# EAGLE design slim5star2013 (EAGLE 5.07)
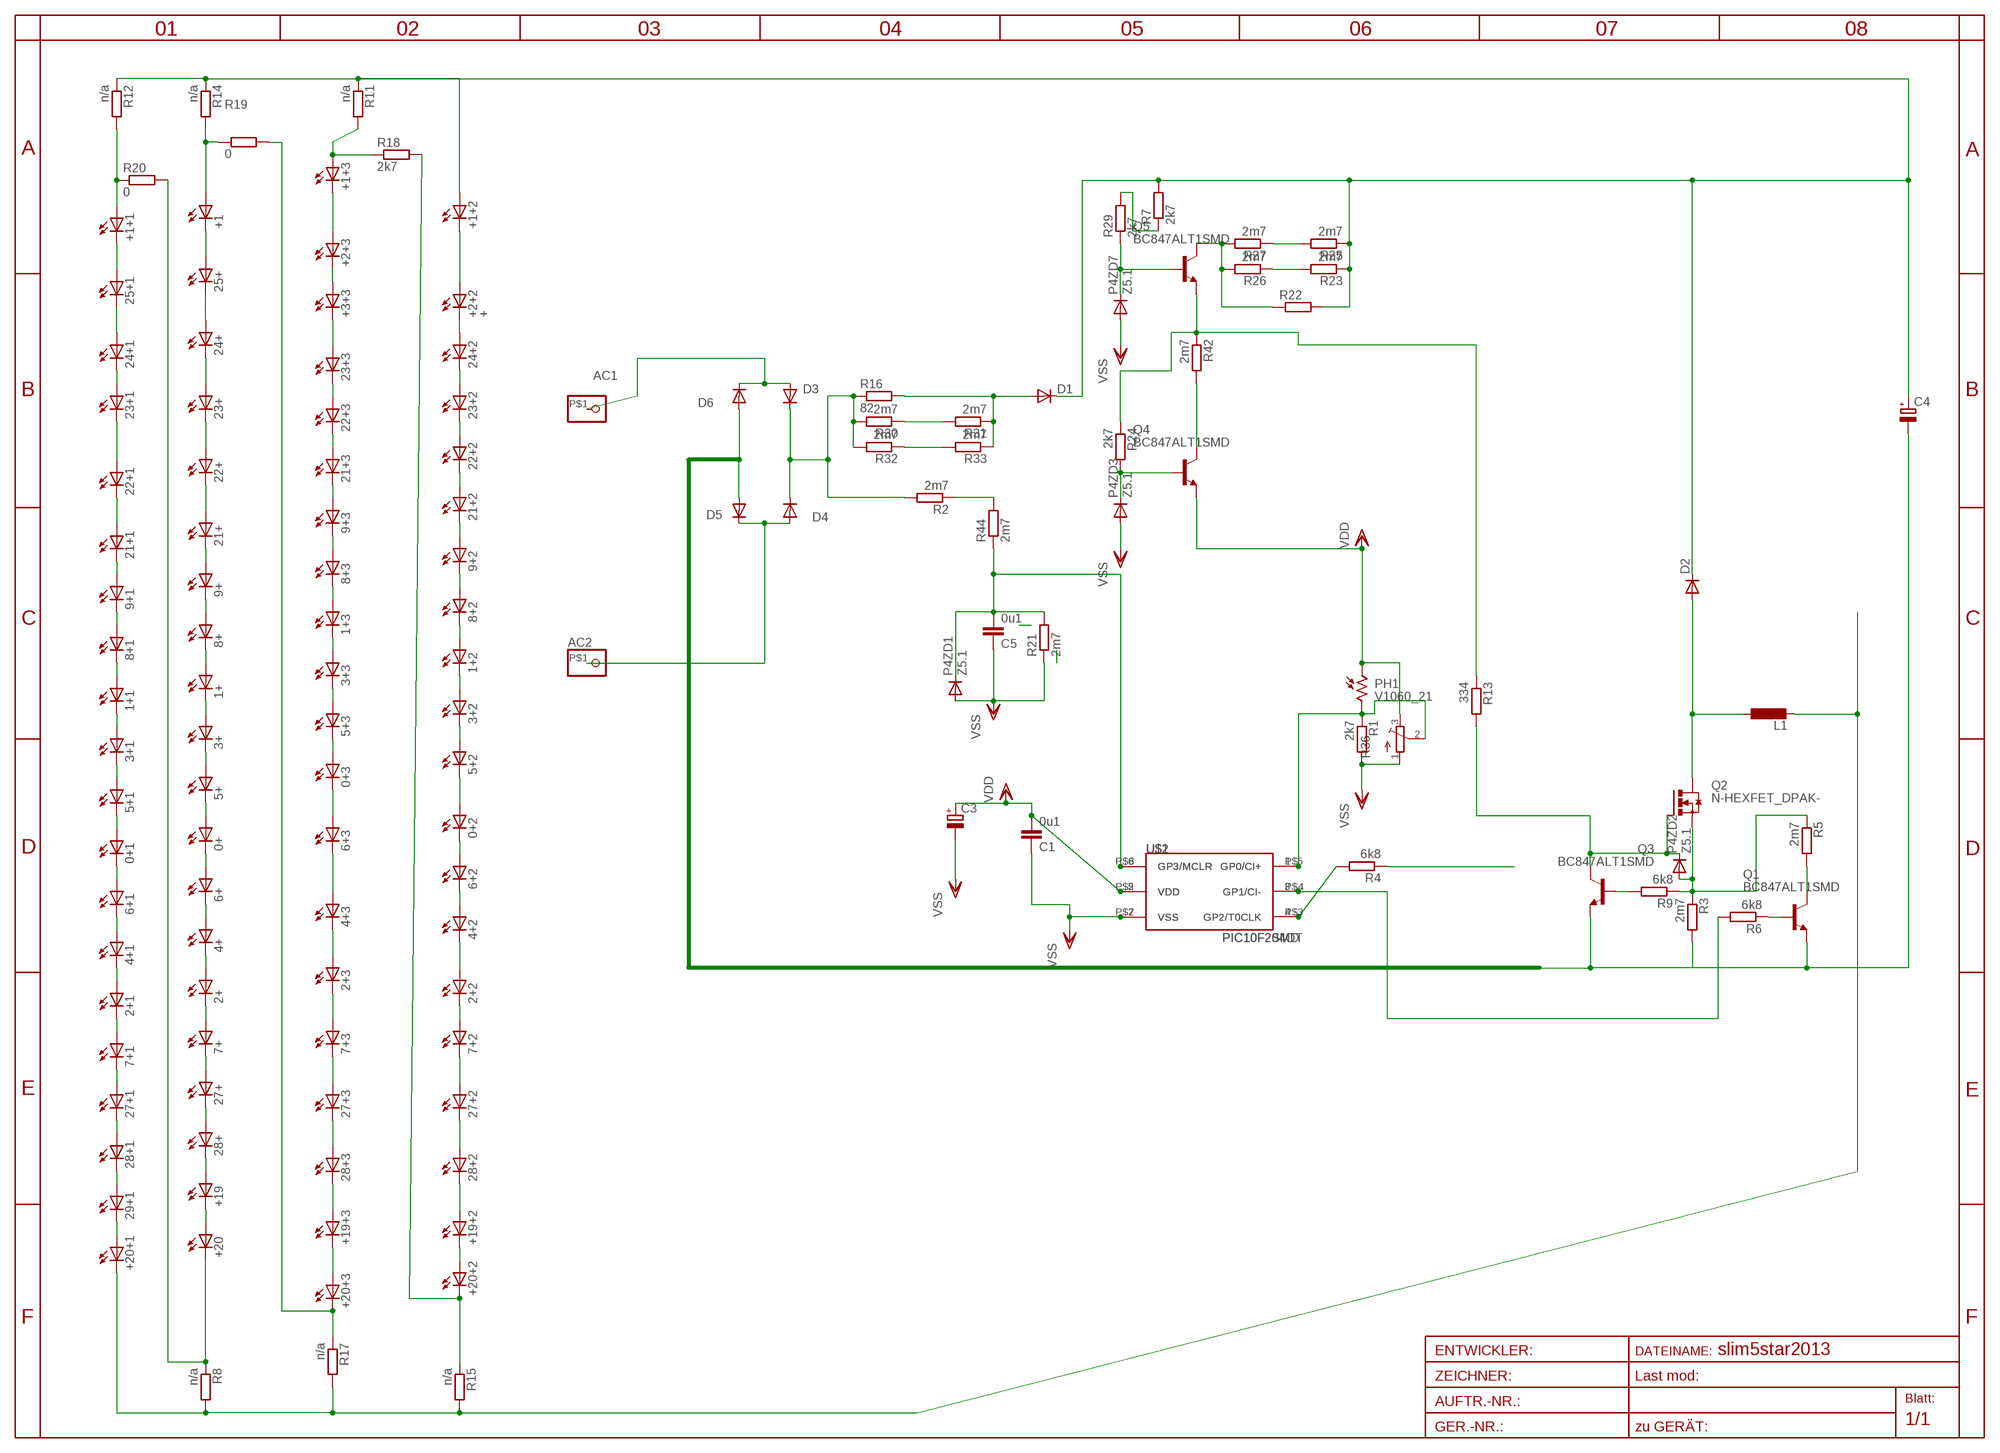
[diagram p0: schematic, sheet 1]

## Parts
0+  LED1210  [1210]
0+1  LED1210  [1210]
0+2  LED1210  [1210]
0+3  LED1210  [1210]
1+  LED1210  [1210]
1+1  LED1210  [1210]
1+2  LED1210  [1210]
1+3  LED1210  [1210]
2+  LED1210  [1210]
2+1  LED1210  [1210]
2+2  LED1210  [1210]
2+3  LED1210  [1210]
3+  LED1210  [1210]
3+1  LED1210  [1210]
3+2  LED1210  [1210]
3+3  LED1210  [1210]
4+  LED1210  [1210]
4+1  LED1210  [1210]
4+2  LED1210  [1210]
4+3  LED1210  [1210]
5+  LED1210  [1210]
5+1  LED1210  [1210]
5+2  LED1210  [1210]
5+3  LED1210  [1210]
6+  LED1210  [1210]
6+1  LED1210  [1210]
6+2  LED1210  [1210]
6+3  LED1210  [1210]
7+  LED1210  [1210]
7+1  LED1210  [1210]
7+2  LED1210  [1210]
7+3  LED1210  [1210]
8+  LED1210  [1210]
8+1  LED1210  [1210]
8+2  LED1210  [1210]
8+3  LED1210  [1210]
9+  LED1210  [1210]
9+1  LED1210  [1210]
9+2  LED1210  [1210]
9+3  LED1210  [1210]
21+  LED1210  [1210]
21+1  LED1210  [1210]
21+2  LED1210  [1210]
21+3  LED1210  [1210]
22+  LED1210  [1210]
22+1  LED1210  [1210]
22+2  LED1210  [1210]
22+3  LED1210  [1210]
23+  LED1210  [1210]
23+1  LED1210  [1210]
23+2  LED1210  [1210]
23+3  LED1210  [1210]
24+  LED1210  [1210]
24+1  LED1210  [1210]
24+2  LED1210  [1210]
25+  LED1210  [1210]
25+1  LED1210  [1210]
27+  LED1210  [1210]
27+1  LED1210  [1210]
27+2  LED1210  [1210]
27+3  LED1210  [1210]
28+  LED1210  [1210]
28+1  LED1210  [1210]
28+2  LED1210  [1210]
28+3  LED1210  [1210]
29+1  LED1210  [1210]
+1  LED1210  [1210]
+1+1  LED1210  [1210]
+1+2  LED1210  [1210]
+1+3  LED1210  [1210]
+2+2  +  LED1210  [1210]
+2+3  LED1210  [1210]
+3+3  LED1210  [1210]
+19  LED1210  [1210]
+19+2  LED1210  [1210]
+19+3  LED1210  [1210]
+20  LED1210  [1210]
+20+1  LED1210  [1210]
+20+2  LED1210  [1210]
+20+3  LED1210  [1210]
AC1  PINHD-1X1SMD  [SMD1X1]
AC2  PINHD-1X1SMD  [SMD1X1]
C1  0u1  C-EUC1206  [C1206]
C3  CPOL-EUE  [PANASONIC_E]
C4  CPOL-EUSANYO_SMD_F12  [SANYO-OSCON_SMD_F12]
C5  0u1  C-EUC1206  [C1206]
D1  DIODE-SMA-DO214  [SMA-DO214AC]
D2  DIODE-SMC  [SMC]
D3  DIODE-SOD80C  [SOD80C]
D4  DIODE-SOD80C  [SOD80C]
D5  DIODE-SOD80C  [SOD80C]
D6  DIODE-SOD80C  [SOD80C]
L1  L-EUPIS2816  [PIS2816]
P4ZD1  Z5.1  DIODE-MINIMELF  [MINIMELF]
P4ZD2  Z5.1  DIODE-MINIMELF  [MINIMELF]
P4ZD3  Z5.1  DIODE-MINIMELF  [MINIMELF]
P4ZD7  Z5.1  DIODE-MINIMELF  [MINIMELF]
PH1  V1060_21  [TO-5_V10]
Q1  BC847ALT1SMD  [SOT23]
Q2  N-HEXFET_DPAK-  [TO252]
Q3  BC847ALT1SMD  [SOT23]
Q4  BC847ALT1SMD  [SOT23]
Q5  BC847ALT1SMD  [SOT23]
R1  2k7  R-EU_R1206  [R1206]
R2  2m7  R-EU_R2010  [R2010]
R3  2m7  R-EU_R1206  [R1206]
R4  6k8  R-EU_R1206  [R1206]
R5  2m7  R-EU_R1210  [R1210]
R6  6k8  R-EU_R0805  [R0805]
R7  2k7  R-EU_R1206  [R1206]
R8  n/a  R-EU_R0402  [R0402]
R9  6k8  R-EU_R0805  [R0805]
R11  n/a  R-EU_R0402  [R0402]
R12  n/a  R-EU_R0402  [R0402]
R13  334  R-EU_R1206  [R1206]
R14  n/a  R-EU_R0402  [R0402]
R15  n/a  R-EU_R0402  [R0402]
R16  82  R-EU_SMD15  [SMDCARB15]
R17  n/a  R-EU_R0402  [R0402]
R18  2k7  R-EU_R0402  [R0402]
R19  0  R-EU_R0402  [R0402]
R20  0  R-EU_R0402  [R0402]
R21  2m7  R-EU_R1206  [R1206]
R22  R-EU_SMD15  [SMDCARB15]
R23  2m7  R-EU_R1210  [R1210]
R24  2k7  R-EU_R1206  [R1206]
R25  2m7  R-EU_R1210  [R1210]
R26  2m7  R-EU_R1210  [R1210]
R27  2m7  R-EU_R1210  [R1210]
R29  2k7  R-EU_R1206  [R1206]
R30  2m7  R-EU_R1210  [R1210]
R31  2m7  R-EU_R1210  [R1210]
R32  2m7  R-EU_R1210  [R1210]
R33  2m7  R-EU_R1210  [R1210]
R36  TRIM_EU-SM-42/43A  [SM-42/43A]
R42  2m7  R-EU_R1206  [R1206]
R44  2m7  R-EU_R2010  [R2010]
U$1  PIC10F2SMD  [DIL8SMD]
U$2  PIC10F204OT  [SOT23-6]

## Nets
AC1: Q5.2(E) R13.1 R24.1 R42.1
AC2: AC2.P$1 D4.A D5.C
BATT-: C4.- D5.A D6.A Q1.2(E) Q3.2(E) R3.2
D+: +1+2.P$1(A) C4.+ D1.K(C) D2.C R7.2 R11.1 R12.1 R14.1 R22.P$2 R23.1 R25.1
MINUS: +20+1.P$2(C) L1.2 R8.2 R15.2 R17.2
N$1: +1+3.P$1(A) R11.2 R18.1
N$2: +1+1.P$1(A) R12.2 R20.1
N$4: +20+3.P$2(C) R17.1 R19.2
N$5: Q4.3(C) R42.2
N$6: 8+.P$1(A) 9+.P$2(C)
N$7: +19.P$2(C) +20.P$1(A)
N$8: 28+.P$2(C) +19.P$1(A)
N$9: 27+.P$2(C) 28+.P$1(A)
N$10: 29+1.P$2(C) +20+1.P$1(A)
N$11: 28+1.P$2(C) 29+1.P$1(A)
N$12: 2+.P$2(C) 7+.P$1(A)
N$13: 7+.P$2(C) 27+.P$1(A)
N$14: 2+.P$1(A) 4+.P$2(C)
N$15: 4+.P$1(A) 6+.P$2(C)
N$16: 0+.P$2(C) 6+.P$1(A)
N$17: 0+.P$1(A) 5+.P$2(C)
N$18: 3+.P$2(C) 5+.P$1(A)
N$19: 1+.P$2(C) 3+.P$1(A)
N$20: 1+.P$1(A) 8+.P$2(C)
N$21: 27+1.P$2(C) 28+1.P$1(A)
N$22: 2+1.P$1(A) 4+1.P$2(C)
N$23: 9+.P$1(A) 21+.P$2(C)
N$24: 21+.P$1(A) 22+.P$2(C)
N$25: 22+.P$1(A) 23+.P$2(C)
N$26: 24+.P$1(A) 25+.P$2(C)
N$27: 25+.P$1(A) +1.P$2(C)
N$28: 23+.P$1(A) 24+.P$2(C)
N$29: 4+1.P$1(A) 6+1.P$2(C)
N$30: 0+1.P$2(C) 6+1.P$1(A)
N$31: 0+1.P$1(A) 5+1.P$2(C)
N$32: 3+1.P$2(C) 5+1.P$1(A)
N$33: 1+1.P$2(C) 3+1.P$1(A)
N$34: 1+1.P$1(A) 8+1.P$2(C)
N$35: 9+1.P$1(A) 21+1.P$2(C)
N$36: 21+1.P$1(A) 22+1.P$2(C)
N$37: 22+1.P$1(A) 23+1.P$2(C)
N$38: 25+1.P$1(A) +1+1.P$2(C)
N$39: 24+1.P$1(A) 25+1.P$2(C)
N$40: 23+1.P$1(A) 24+1.P$2(C)
N$41: 2+1.P$2(C) 7+1.P$1(A)
N$42: 7+1.P$2(C) 27+1.P$1(A)
N$43: 8+1.P$1(A) 9+1.P$2(C)
N$45: +1.P$1(A) R14.2 R19.1
N$46: +19+2.P$2(C) +20+2.P$1(A)
N$47: 28+2.P$2(C) +19+2.P$1(A)
N$48: 27+2.P$2(C) 28+2.P$1(A)
N$49: 2+2.P$1(A) 4+2.P$2(C)
N$50: 4+2.P$1(A) 6+2.P$2(C)
N$51: 0+2.P$2(C) 6+2.P$1(A)
N$52: 0+2.P$1(A) 5+2.P$2(C)
N$53: 3+2.P$2(C) 5+2.P$1(A)
N$54: 1+2.P$2(C) 3+2.P$1(A)
N$55: 1+2.P$1(A) 8+2.P$2(C)
N$56: 9+2.P$1(A) 21+2.P$2(C)
N$57: 21+2.P$1(A) 22+2.P$2(C)
N$58: 22+2.P$1(A) 23+2.P$2(C)
N$59: +1+2.P$2(C) +2+2.P$1(A)
N$60: 24+2.P$1(A) +2+2.P$2(C)
N$61: 23+2.P$1(A) 24+2.P$2(C)
N$62: 2+2.P$2(C) 7+2.P$1(A)
N$63: 7+2.P$2(C) 27+2.P$1(A)
N$64: 8+2.P$1(A) 9+2.P$2(C)
N$65: +20+2.P$2(C) R15.1 R18.2
N$66: +20.P$2(C) R8.1 R20.2
N$67: +19+3.P$2(C) +20+3.P$1(A)
N$68: 28+3.P$2(C) +19+3.P$1(A)
N$69: 27+3.P$2(C) 28+3.P$1(A)
N$70: 2+3.P$1(A) 4+3.P$2(C)
N$71: 4+3.P$1(A) 6+3.P$2(C)
N$72: 0+3.P$2(C) 6+3.P$1(A)
N$73: 0+3.P$1(A) 5+3.P$2(C)
N$74: 3+3.P$2(C) 5+3.P$1(A)
N$75: 1+3.P$2(C) 3+3.P$1(A)
N$76: 1+3.P$1(A) 8+3.P$2(C)
N$77: 9+3.P$1(A) 21+3.P$2(C)
N$78: 21+3.P$1(A) 22+3.P$2(C)
N$79: 22+3.P$1(A) 23+3.P$2(C)
N$80: +1+3.P$2(C) +2+3.P$1(A)
N$81: +2+3.P$2(C) +3+3.P$1(A)
N$82: 23+3.P$1(A) +3+3.P$2(C)
N$83: 2+3.P$2(C) 7+3.P$1(A)
N$84: 7+3.P$2(C) 27+3.P$1(A)
N$85: 8+3.P$1(A) 9+3.P$2(C)
N$86: D1.A R16.P$2 R31.1 R33.1
N$87: D2.A L1.1 Q2.3(D)
N$88: PH1.2 R1.1 R36.2(S) U$1.P$5(GP0/CI+) U$2.1(GP0/CI+)
N$91: D3.C D4.C R2.2 R16.P$1 R30.2 R32.2
N$92: Q5.3(C) R22.P$1 R26.2 R27.2
N$93: AC1.P$1 D3.A D6.C
N$94: P4ZD2.C Q2.1(G) Q3.3(C) R13.2
N$95: R4.2 U$1.P$3(GP2/T0CLK) U$2.4(GP2/T0CLK)
N$96: C5.2 P4ZD1.C R21.2 R44.1 U$1.P$8(GP3/MCLR) U$2.6(GP3/MCLR)
N$97: R2.1 R44.2
N$98: Q1.1(B) R6.1
N$99: R23.2 R26.1
N$100: R25.2 R27.1
N$101: Q1.3(C) R5.2
N$102: R6.2 U$1.P$4(GP1/CI-) U$2.3(GP1/CI-)
N$103: P4ZD3.C Q4.1(B) R24.2
N$104: P4ZD7.C Q5.1(B) R29.1
N$105: P4ZD2.A Q2.2(S) R3.1 R5.1 R9.1
N$106: R7.1 R29.2
N$107: R30.1 R31.2
N$108: R32.1 R33.2
N$109: Q3.1(B) R9.2
PIR: R4.1
VDD: C1.2 C3.+ PH1.1 Q4.2(E) R36.3(E) U$1.P$2(VDD) U$2.5(VDD)
VSS: C1.1 C3.- C5.1 P4ZD1.A P4ZD3.A P4ZD7.A R1.2 R21.1 R36.1(A) U$1.P$7(VSS) U$2.2(VSS)

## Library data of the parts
0+ 0+1-0+3 1+ 1+1-1+3 2+ 2+1-2+3 3+ 3+1-3+3 4+ 4+1-4+3 5+ 5+1-5+3 6+ 6+1-6+3 7+ 7+1-7+3 8+ 8+1-8+3 9+ 9+1-9+3 21+ 21+1-21+3 22+ 22+1-22+3 23+ 23+1-23+3 24+ 24+1 24+2 25+ 25+1 27+ 27+1-27+3 28+ 28+1-28+3 29+1 +1 +1+1-+1+3 +2+2 +2+3 +3+3 +19 +19+2 +19+3 +20 +20+1-+20+3 = led(2):LED: LED
AC1 AC2 = pinhead:PINHD-1X1: PIN HEADER
C1 C5 = rcl:C-EU: CAPACITOR, European symbol
C3 C4 = rcl-2:CPOL-EU: POLARIZED CAPACITOR, European symbol
D1-D6 P4ZD1-P4ZD3 P4ZD7 = diode:DIODE-: DIODE
L1 = rcl:L-EU: INDUCTOR, European symbol
PH1 = photo-elements:?1060*: Sensor Street Light control
Q1 Q3-Q5 = transistor-npn:BC847*: NPN Transistor
Q2 = transistor-power:N-HEXFET_?-*: HEXFET® Power MOSFET
R1 R2 R4 R7 R8 R11-R15 R17-R21 R23-R27 R29-R33 R42 R44 = rcl-2:R-EU_: RESISTOR, European symbol
R3 R5 R6 R9 R16 R22 = rcl:R-EU_: RESISTOR, European symbol
R36 = pot:TRIM_EU-: POTENTIOMETER
U$1 U$2 = microchip-5:PIC10F2*: uPC nW 0,25/0,5k Program Flash memory Comparator

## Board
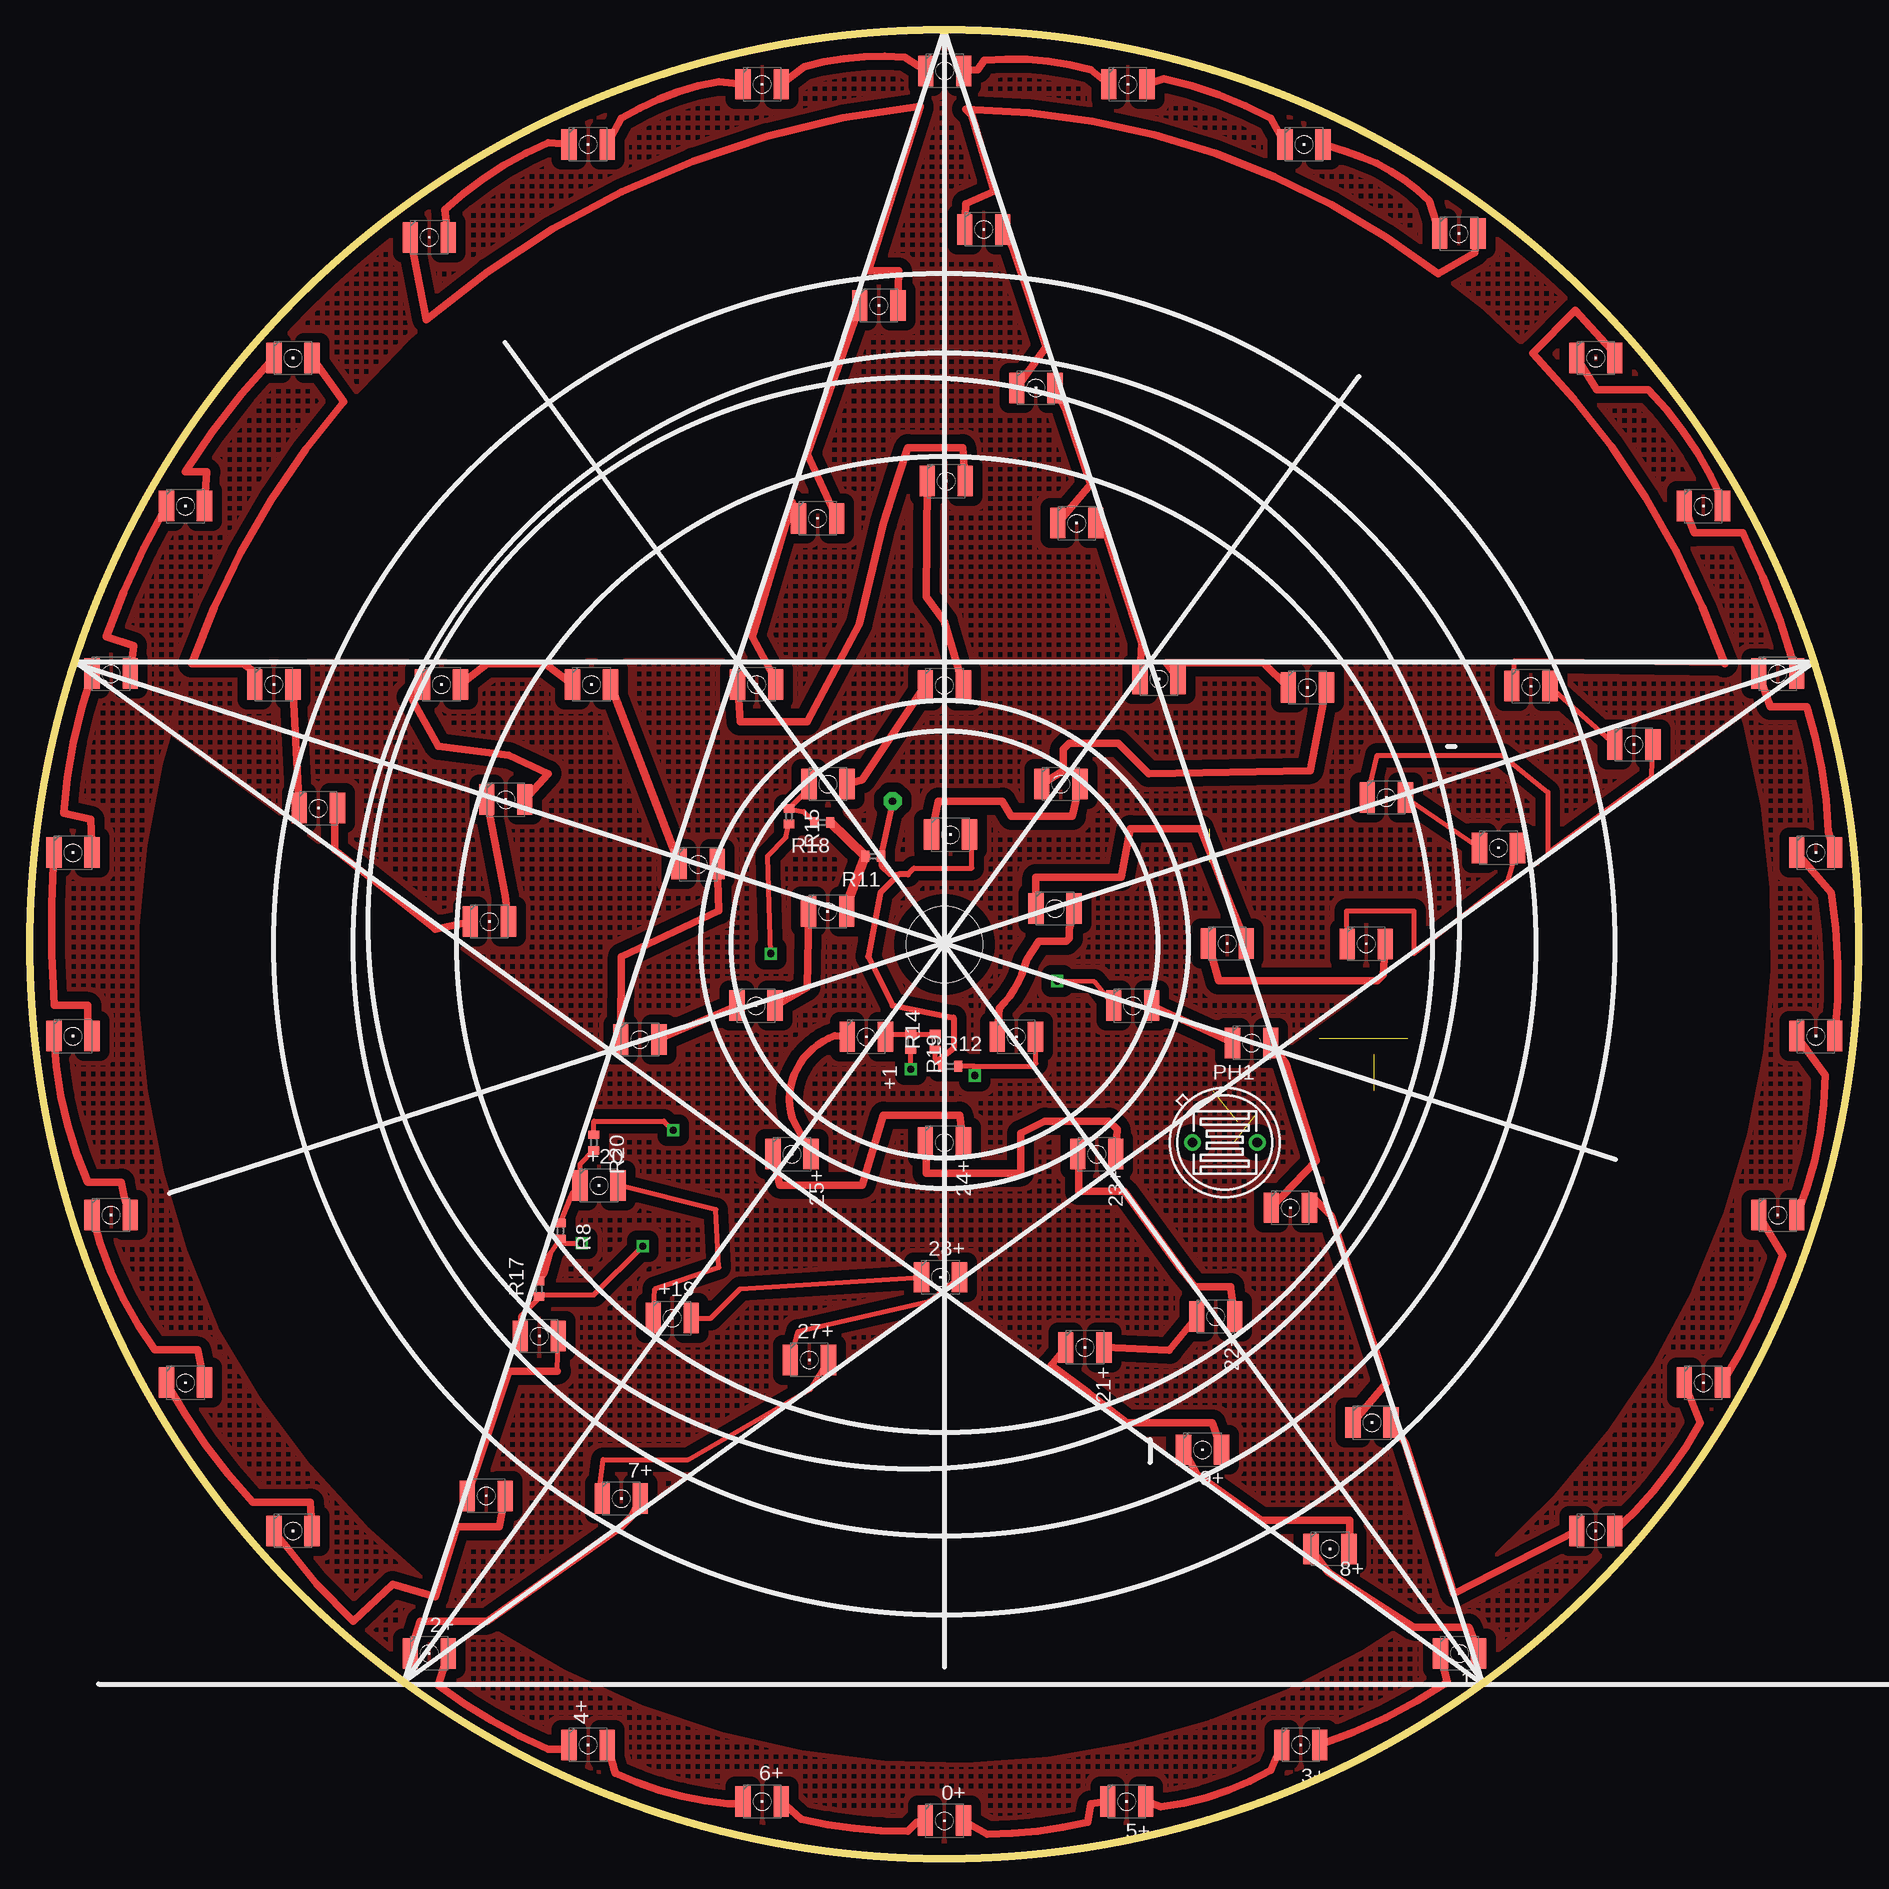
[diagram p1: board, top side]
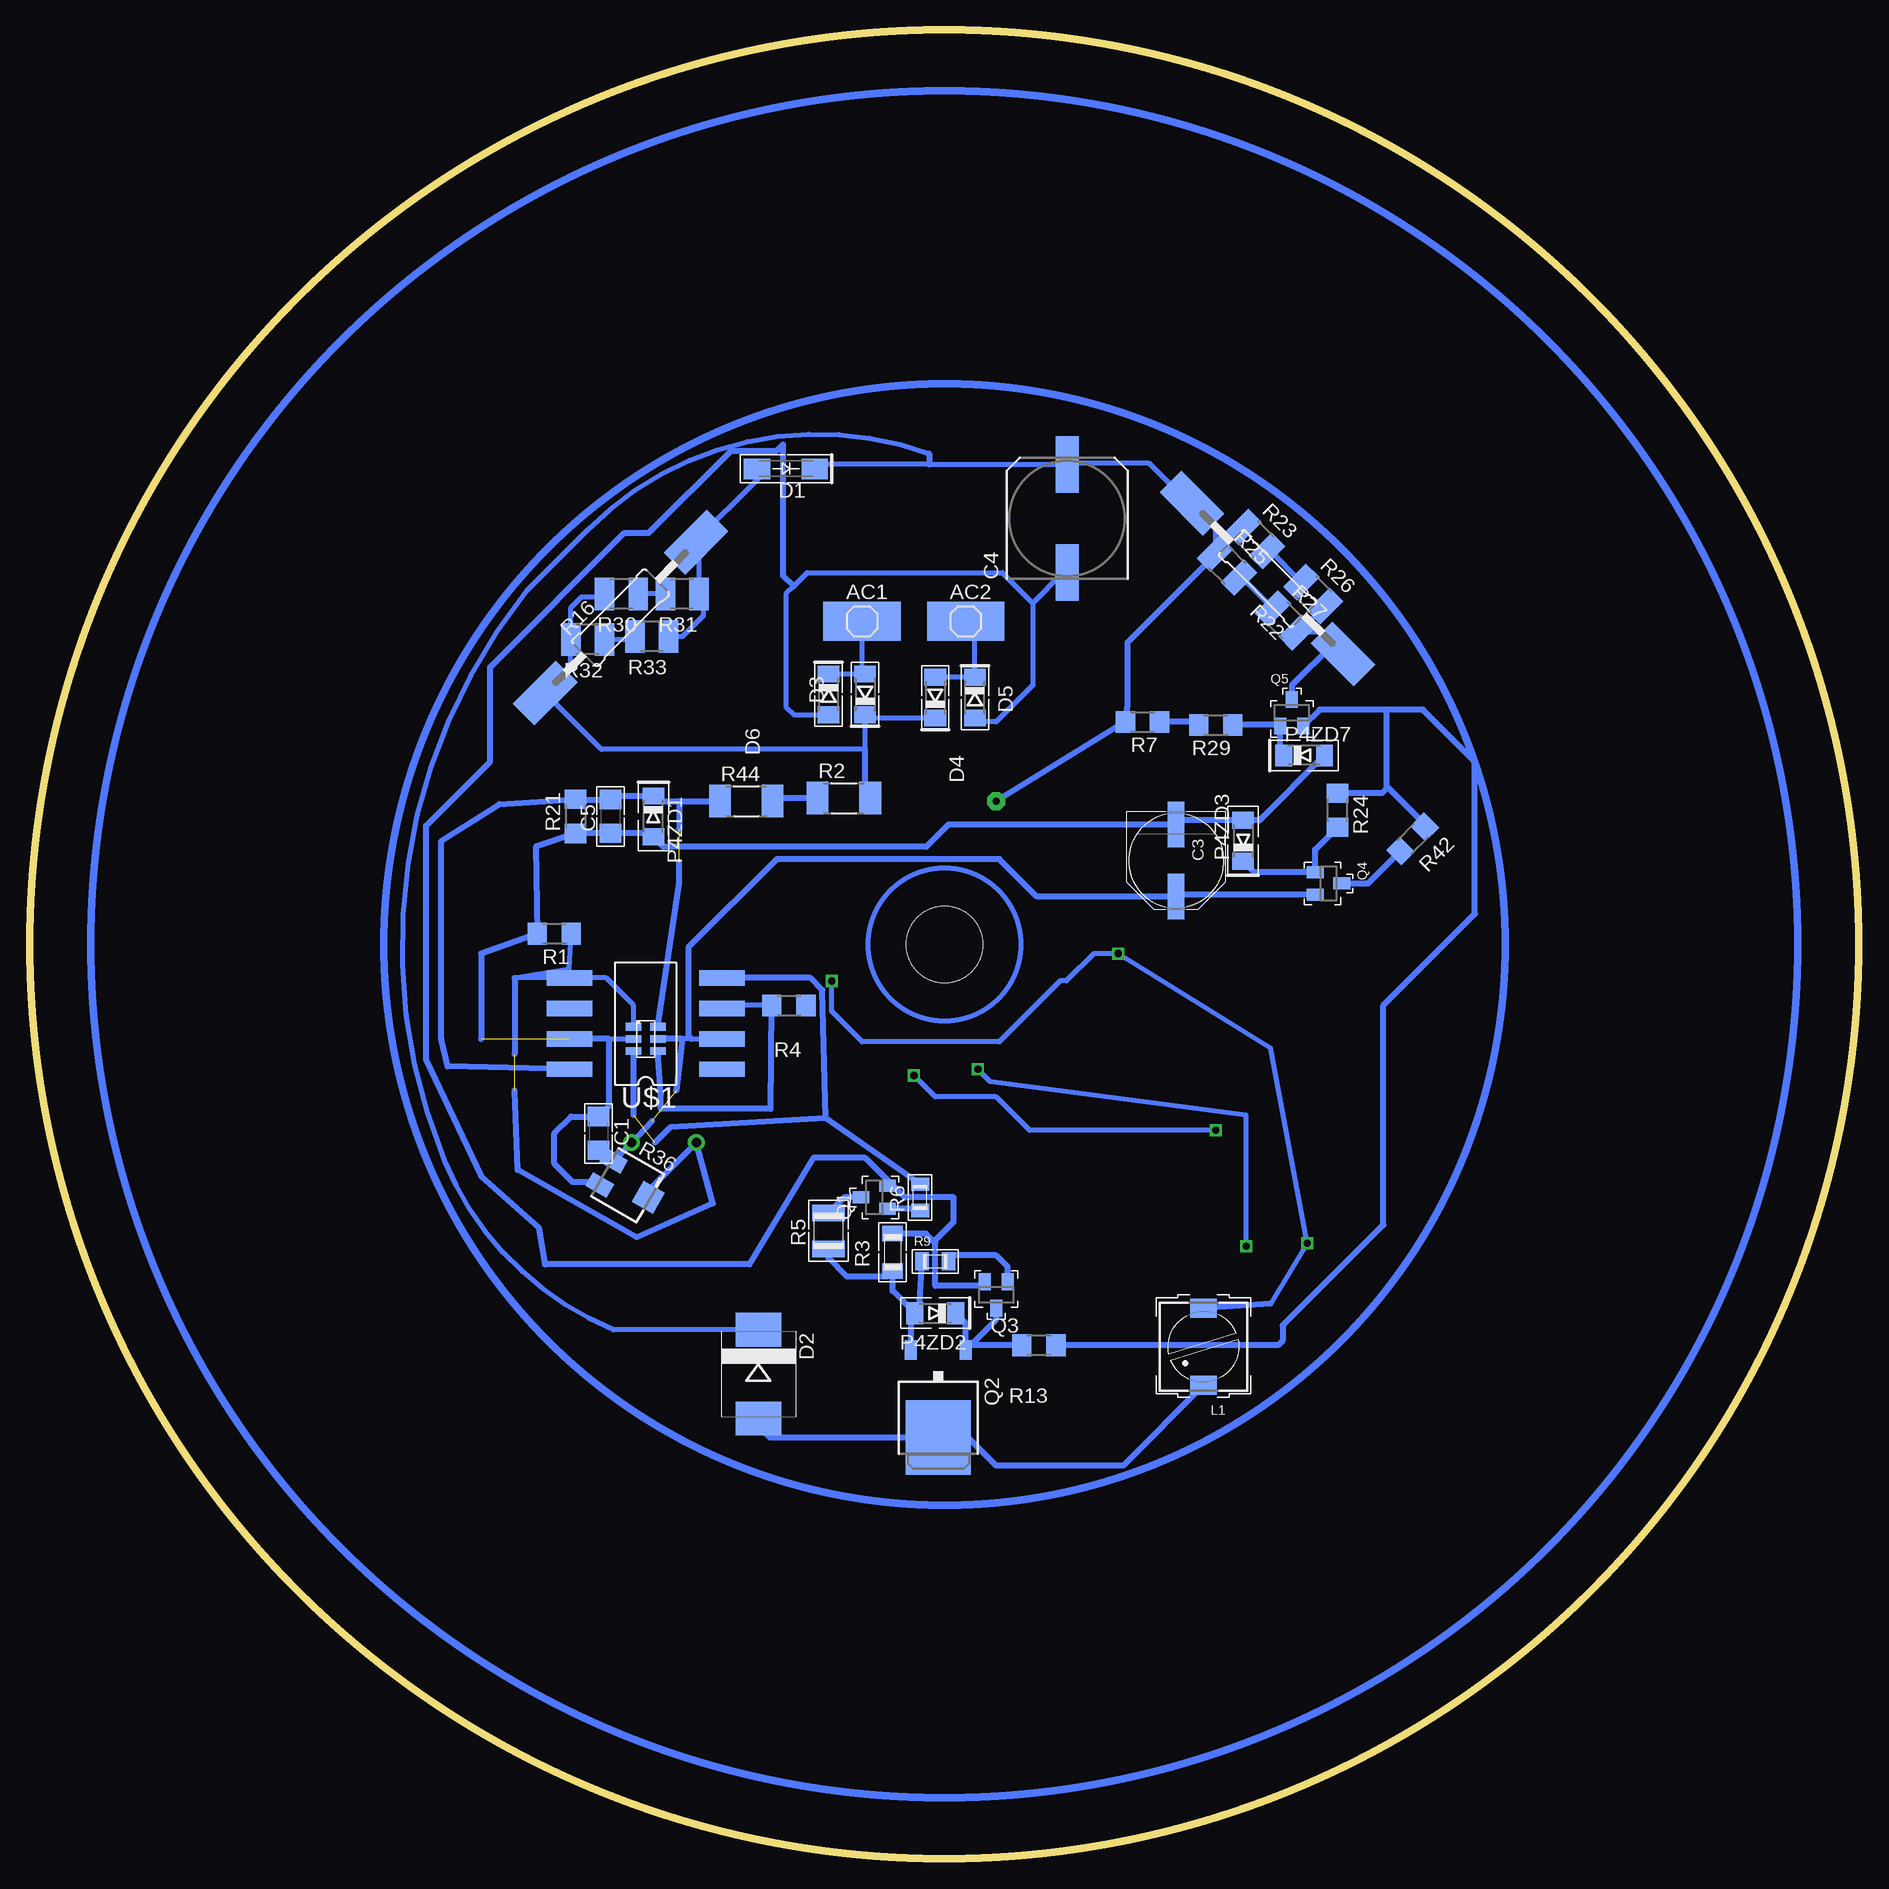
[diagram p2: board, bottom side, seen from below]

Size 152.4 x 152.4 mm. Coordinates in mm from the lower left corner, seen from the top.
Outline: circle at 76.2,76.2 radius 76.2
Copper layers (1*16): Top 0.035mm / dielectric 1.5mm / Bottom 0.035mm
Design rules "default": minimum track width 10mil, minimum drill 24mil, track to track 8mil, track to pad 8mil, pad to pad 8mil, via to via 8mil, smd to smd 8mil, copper to edge 40mil, drill to drill 8mil, minimum pad ring 10mil, minimum via ring 8mil, stop-mask expansion 4mil, vias tented up to drill 0mil, thermal gap 10mil
Holes 6.35 mm at 76.2,76.2

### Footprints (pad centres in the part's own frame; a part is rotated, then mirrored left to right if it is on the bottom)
1210 = smd 1.27 x 2.54: P$1 1.587,0; P$2 -1.587,0
SMD1X1 = smd 6.452 x 3.251: P$1 0,0
C1206 = smd 1.6 x 1.8: 1 -1.4,0; 2 1.4,0
PANASONIC_E = smd 3.8 x 1.4: + 3,0; - -3,0
SANYO-OSCON_SMD_F12 = smd 4.7 x 1.9: + 4.5,0; - -4.5,0
SMA-DO214AC = smd 2.2 x 1.7: A 2.4,0; K -2.4,0
SMC = smd 2.8 x 3.8: A 3.7,0; C -3.7,0
SOD80C = smd 1.4 x 1.8: A 1.7,0; C -1.7,0
PIS2816 = smd 2.2 x 1.6: 1 0,3.2; 2 0,-3.2
MINIMELF = smd 1.4 x 1.8: A 1.7,0; C -1.7,0
TO-5_V10 = drill 0.8 pad 1.4 round: 1 -2.7,0; 2 2.7,0
SOT23 = smd 1 x 1.4: 1 -0.95,-1.1; 2 0.95,-1.1; 3 0,1.1
TO252 = smd 1 x 1.6: 1 -2.28,-3.53; 2 2.28,-3.53 | smd 5.4 x 6.2: 3 0,3.77
R1206 = smd 1.6 x 1.803: 1 -1.422,0; 2 1.422,0
R2010 = smd 1.8 x 2.7: 1 -2.2,0; 2 2.2,0
R1206' = smd 1.3 x 1.7: 1 -1.55,0; 2 1.55,0
R1210 = smd 1.4 x 2.7: 1 -1.5,0; 2 1.5,0
R0805 = smd 1.1 x 1.5: 1 -1.1,0; 2 1.1,0
R0402 = smd 0.7 x 0.9: 1 -0.65,0; 2 0.65,0
SMDCARB15 = smd 5.08 x 2.54: P$1 -8.89,0; P$2 8.89,0
R1210' = smd 1.6 x 2.7: 1 -1.4,0; 2 1.4,0
SM-42/43A = smd 2 x 1.3: 1 2,1.15; 3 2,-1.15 | smd 2 x 2: 2 -2,0
DIL8SMD = smd 1.27 x 3.81: P$1 -3.81,-6.35; P$2 -1.27,-6.35; P$3 1.27,-6.35; P$4 3.81,-6.35; P$5 3.81,6.35; P$6 1.27,6.35; P$7 -1.27,6.35; P$8 -3.81,6.35
SOT23-6 = smd 0.635 x 1.27: 1 -1.016,-1.016; 2 0,-1.016; 3 1.016,-1.016; 4 1.016,1.016; 5 0,1.016; 6 -1.016,1.016

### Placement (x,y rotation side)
0+  76.2,3.17 0 top
0+1  148.82,83.85 0 top
0+2  61.01,147.88 0 top
0+3  12.95,112.73 0 top
1+  119.13,17.12 0 top
1+1  130.48,125.07 0 top
1+2  106.17,142.88 0 top
1+3  24.03,87.55 0 top
2+  33.27,17.12 0 top
2+1  139.45,39.67 0 top
2+2  70.74,129.44 0 top
2+3  3.58,68.55 0 top
3+  105.89,9.5 0 top
3+1  139.45,112.73 0 top
3+2  91.49,147.88 0 top
3+3  20.32,97.87 0 top
4+  46.51,9.5 0 top
4+1  145.64,53.64 0 top
4+2  33.27,135.13 0 top
4+3  3.58,83.85 0 top
5+  91.39,4.78 0 top
5+1  145.64,98.76 0 top
5+2  76.23,149 0 top
5+3  21.92,125.07 0 top
6+  61.01,4.78 0 top
6+1  148.82,68.55 0 top
6+2  46.51,142.88 0 top
6+3  6.76,98.76 0 top
7+  49.28,30.02 0 top
7+1  130.48,27.33 0 top
7+2  65.63,111.71 0 top
7+3  6.76,53.64 0 top
8+  108.33,25.83 0 top
8+1  125.07,97.71 0 top
8+2  119.08,135.43 0 top
8+3  38.28,78.11 0 top
9+  97.71,34.09 0 top
9+1  133.65,92.86 0 top
9+2  79.48,135.79 0 top
9+3  39.65,88.27 0 top
21+  87.91,42.62 0 top
21+1  113.03,88.44 0 top
21+2  83.82,122.58 0 top
21+3  34.29,97.87 0 top
22+  98.81,45.19 0 top
22+1  122.38,84.25 0 top
22+2  87.22,111.3 0 top
22+3  46.79,97.87 0 top
23+  88.9,58.72 0 top
23+1  111.35,76.25 0 top
23+2  94.08,98.32 0 top
23+3  55.68,82.88 0 top
24+  76.2,59.69 0 top
24+1  99.77,76.28 0 top
24+2  106.45,97.61 0 top
25+  63.5,58.72 0 top
25+1  85.42,79.2 0 top
27+  64.95,41.58 0 top
27+1  111.84,36.35 0 top
27+2  60.55,97.87 0 top
27+3  12.95,39.67 0 top
28+  75.87,48.46 0 top
28+1  105.03,54.25 0 top
28+2  76.35,114.81 0 top
28+3  21.92,27.33 0 top
29+1  101.8,68 0 top
+1  69.7,68.5 0 top
+1+1  82.19,68.5 0 top
+1+2  76.71,85.34 0 top
+1+3  66.47,78.94 0 top
+2+2  85.9,89.56 0 top
+2+3  60.5,71.09 0 top
+3+3  50.83,68.28 0 top
+19  53.52,45.06 0 top
+19+2  76.2,97.79 0 top
+19+3  38.02,30.25 0 top
+20  47.42,56.11 0 top
+20+1  91.9,71.09 0 top
+20+2  66.5,89.56 0 top
+20+3  42.44,43.56 0 top
AC1  83.06,103.12 0 bottom
AC2  74.42,103.12 0 bottom
C1  105.03,60.45 270 bottom
C3  56.9,83.19 270 bottom
C4  65.97,111.7 90 bottom
C5  104.01,86.87 90 bottom
D1  89.41,115.82 180 bottom
D2  91.69,40.39 270 bottom
D3  82.8,97.03 90 bottom
D4  76.96,96.77 90 bottom
D5  73.66,96.77 270 bottom
D6  85.85,97.03 270 bottom
L1  54.61,42.67 180 bottom
P4ZD1  100.46,86.87 270 bottom
P4ZD2  76.96,45.47 180 bottom
P4ZD3  51.31,84.84 90 bottom
P4ZD7  46.23,91.95 0 bottom
PH1  99.57,59.69 180 top
Q1  82.04,55.12 90 bottom
Q2  76.71,38.86 180 bottom
Q3  71.88,46.99 180 bottom
Q4  44.2,81.28 270 bottom
Q5  47.24,95.5 0 bottom
R1  108.71,77.09 180 bottom
R2  84.58,88.39 0 bottom
R3  2m7  [R1206']  80.52,50.55 90 bottom
R4  89.15,71.12 180 bottom
R5  85.85,52.32 90 bottom
R6  78.23,55.12 90 bottom
R7  59.69,94.74 180 bottom
R8  44.2,52.32 270 top
R9  76.96,49.78 0 bottom
R11  70.26,83.55 180 top
R12  76.71,66.04 0 top
R13  68.33,42.8 180 bottom
R14  75.44,68.07 90 top
R15  63.25,86.87 270 top
R16  103.18,103.43 45 bottom
R17  42.42,47.5 90 top
R18  66.04,86.36 180 top
R19  73.41,68.07 270 top
R20  46.99,59.69 270 top
R21  106.93,86.87 90 bottom
R22  49.28,106.68 135 bottom
R23  2m7  [R1210']  50.29,109.98 315 bottom
R24  43.43,87.38 270 bottom
R25  2m7  [R1210']  52.65,107.77 315 bottom
R26  2m7  [R1210']  45.47,105.41 315 bottom
R27  2m7  [R1210']  47.83,103.2 315 bottom
R29  53.59,94.49 180 bottom
R30  2m7  [R1210']  103.12,105.41 180 bottom
R31  2m7  [R1210']  98.04,105.41 180 bottom
R32  2m7  [R1210']  105.92,101.6 180 bottom
R33  2m7  [R1210']  100.58,101.85 180 bottom
R36  102.62,56.13 150 bottom
R42  37.19,84.98 225 bottom
R44  92.71,88.14 0 bottom
U$1  101.09,69.6 90 bottom
U$2  101.09,68.33 270 bottom

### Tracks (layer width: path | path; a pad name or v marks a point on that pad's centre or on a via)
AC1
  Bottom 0.5: R13.1 48.39,42.8 48.01,43.18 48.01,44.45 39.62,52.83 39.62,71.12 32,78.74 32,91.44 36.32,95.76 39.37,95.76 | 39.37,95.76 44.94,95.76 Q5.2 | R42.1 36.18,86.22 39.24,89.28 | 39.24,89.28 39.37,89.41 39.37,95.76 | R24.1 39.73,88.8 39.24,89.28
AC2
  Bottom 0.406: AC2.P$1 73.66,103.12 D5.C D4.A
BATT-
  Bottom 0.406: D6.A 88.72,95.33 89.41,96.01 89.41,105.41 88.77,106.05 87.63,107.19 71.37,107.19 68.83,104.65 | 68.83,104.65 68.83,97.79 71.88,94.74 73.33,94.74 D5.A | C4.- 66.28,107.2 68.83,104.65
  Bottom 0.5: R3.2 77.75,52.1 77.09,51.44 | 77.09,51.44 76.96,51.31 76.96,47.75 73.17,47.75 Q3.2 | 80.45,56.07 Q1.2 | 80.45,56.07 79.5,55.12 75.44,55.12 75.44,53.09 77.09,51.44 | 80.45,56.07 82.8,58.42 87.12,58.42 92.46,49.53 109.47,49.53 109.98,52.58 114.81,56.9 119.38,66.55 119.38,86.11 114.05,91.44 114.05,99.31 102.87,110.49 100.84,110.49 93.98,117.35 90.17,117.35 89.66,117.86 89.66,106.93 88.77,106.05
D+  (via drill 0.6 pad 1.5)
  Top 0.406: R14.1 75.44,66.66 75.62,66.48 R12.1 | R11.1 70.91,82.76 71.63,82.04 73.15,82.04 73.66,82.55 78.49,82.55 78.49,85.15 +1+2.P$1
  Top 0.5: 73.15,82.04 72.39,82.04 70.87,80.52 69.85,75.18 71.88,71.12 76.96,70.1 76.96,67.56 75.62,66.48 | v71.88,88.14 R11.1
  Bottom 0.406: R23.1 53.49,108.76 R25.1 53.64,111.05 R22.P$2 55.82,112.97 59.18,116.33 65.84,116.33 C4.+ 77.47,116.2 87.33,116.2 D1.K | D2.C 103.78,44.09 arc45 117.86,58.17 arc61 111,105.66 105.92,110.74 arc65 77.47,117.09
  Bottom 0.5: R25.1 53.64,108.66 60.96,101.35 60.96,96.16 R7.2 v71.88,88.14 | 77.47,117.09 77.47,116.2
MINUS  (via drill 0.6)
  Top 0.406: R15.2 62.99,85.09 61.47,83.57 v61.72,75.44 | 43.32,50.43 R17.2 42.93,48.77 43.43,50.55 R8.2 44.56,51.31 v45.97,51.31 | +20+1.P$2 88.67,73.13 v85.6,73.15
  Bottom 0.406: v85.6,73.15 85.6,70.61 83.06,68.07 71.63,68.07 66.55,73.15 66.04,73.15 63.75,75.44 v61.72,75.44 49.02,67.56 v45.97,51.31 49.02,46.27
  Bottom 0.5: 49.02,46.27 L1.2
N$1
  Top 0.813: R18.1 R11.2 68.07,79.5 +1+3.P$1
N$2  (via drill 0.6)
  Top 0.406: 78.74,66.04 R12.2 | 78.74,66.04 83.57,66.04 83.82,66.29 83.82,68.47 +1+1.P$1 | R20.1 46.99,61.47 52.83,61.47 v53.59,60.71 | v78.74,65.28 78.74,66.04
  Bottom 0.406: v53.59,60.71 69.09,60.71 71.88,63.5 76.96,63.5 v78.74,65.28
N$3
  pour Top (isolate 0.813, hatched): 48.31,66.78 31.24,14.66 76.33,47.45 120.95,14.66 104.27,67.36 148.74,99.77 93.29,99.72 76.2,152.4 59.18,99.87 3.76,99.75
N$4  (via drill 0.6)
  Top 0.406: 42.53,46.85 R17.1 | 42.53,46.85 40.89,45.21 40.89,43.6 +20+3.P$2 | 42.53,46.85 42.67,46.99 46.99,46.99 v51.05,51.05 | v73.41,65.79 R19.2
  Bottom 0.406: v51.05,51.05 51.05,61.98 72.39,64.77 v73.41,65.79
N$5
  Bottom 0.5: Q4.3 40.89,81.28 R42.2
N$6
  Top 0.61: 8+.P$1 109.98,28.19 102.62,28.19 97.28,32 9+.P$2
N$7
  Top 0.406: +19.P$2 52.07,47.5 57.4,49.28 57.15,54.1 +20.P$1
N$8
  Top 0.406: +19.P$1 56.74,45.06 59.18,47.5 28+.P$2
N$9
  Top 0.406: 28+.P$1 74.93,46.48 64.01,43.94 27+.P$2
N$10
  Top 0.61: +20+1.P$1 29+1.P$2
N$11
  Top 0.61: 28+1.P$2 107.19,58.17 104.65,66.29 29+1.P$1
N$12
  Top 0.61: 7+.P$1 50.1,28.51 49.28,27.69 38.1,19.81 32.51,19.81 2+.P$2
N$13
  Top 0.406: 27+.P$1 65.02,39.12 54.86,33.27 47.75,33.27 47.5,30.99 47.75,30.99 48.01,30.48 7+.P$2
N$14
  Top 0.61: 2+.P$1 34.04,14.48 arc14 43.18,9.14 44.92,9.14 4+.P$2
N$15
  Top 0.61: 4+.P$1 48.77,7.11 arc19 58.17,4.57 59.22,4.57 6+.P$2
N$16
  Top 0.61: 6+.P$1 64.26,3.3 arc13 73.15,2.29 73.91,3.05 0+.P$2
N$17
  Top 0.61: 0+.P$1 79.76,2.03 arc13 88.14,3.05 88.39,4.57 5+.P$2
N$18
  Top 0.61: 5+.P$1 94.23,4.32 arc23 103.38,7.37 3+.P$2
N$19
  Top 0.61: 3+.P$1 arc16 118.11,14.73 1+.P$2
N$20
  Top 0.61: 1+.P$1 119.89,19.3 115.32,19.3 108.2,23.88 8+.P$2
N$21
  Top 0.61: 27+1.P$2 113.03,39.62 108.46,53.59 106.78,55.27 28+1.P$1
N$22
  Top 0.61: 4+1.P$2 146.05,50.29 arc-13 2+1.P$1
N$23
  Top 0.61: 9+.P$1 98.54,36.34 91.4,36.34 88.1,38.88 88.14,38.86 85.09,41.15 21+.P$2
N$24
  Top 0.61: 21+.P$1 94.96,42.37 22+.P$2
N$25
  Top 0.61: 22+.P$1 100.08,47.5 100.08,47.69 97.09,47.69 96.01,49.02 91.19,55.63 87.38,55.63 87.38,58.81 23+.P$2
N$26
  Top 0.61: 25+.P$2 62.48,56.13 69.34,56.13 71.12,61.98 77.47,61.98 24+.P$1
N$27
  Top 0.61: +1.P$2 67.06,68.58 arc86 63.5,61.72 25+.P$1
N$28
  Top 0.61: 23+.P$1 90.59,60.8 89.92,61.47 84.58,61.47 82.55,60.45 82.55,57.15 74.68,57.15 74.68,58.74 24+.P$2
N$29
  Top 0.61: 6+1.P$2 149.61,65.28 arc-22 4+1.P$1
N$30
  Top 0.61: 0+1.P$2 150.11,80.52 arc-15 6+1.P$1
N$31
  Top 0.61: 5+1.P$2 145.03,96.01 148.08,96.01 arc-15 149.86,85.6 0+1.P$1
N$32
  Top 0.61: 3+1.P$2 138.68,110.49 142.75,110.49 arc-10 147.07,99.31 5+1.P$1
N$33
  Top 0.61: 1+1.P$2 130.56,122.43 134.87,122.43 arc-21 140.97,113.28 3+1.P$1
N$34
  Top 0.406: 8+1.P$2 123.7,99.82 141.22,99.57
  Top 0.61: 141.22,99.57 arc25 125.22,125.48 128.78,129.03 131.32,126.24 131.83,125.73 1+1.P$1
N$35
  Top 0.406: 9+1.P$1 135.13,90.17 126.49,83.82 126.49,88.9 122.68,91.95 112.27,91.95 21+1.P$2
N$36
  Top 0.406: 21+1.P$1 22+1.P$2
N$37
  Top 0.406: 22+1.P$1 123.19,81.53 115.32,75.44 115.32,78.99 109.73,78.99 23+1.P$2
N$38
  Top 0.61: +1+1.P$2 80.77,70.87 arc31 83.06,74.93 84.07,76.45 86.36,76.45 86.61,76.71 86.61,77.47 25+1.P$1
N$39
  Top 0.61: 25+1.P$2 83.82,81.79 90.93,81.79 91.69,85.85 97.54,85.85 24+1.P$1
N$40
  Top 0.61: 24+1.P$2 99.06,73.15 112.27,73.15 112.78,73.66 23+1.P$1
N$41
  Top 0.61: 2+1.P$2 139.19,36.32 arc-19 7+1.P$1
N$42
  Top 0.61: 7+1.P$2 118.65,22.07 114.61,34.64 27+1.P$1
N$43
  Top 0.406: 8+1.P$1 9+1.P$2
N$44
  pour Top (isolate 0.813, hatched): 76.73,152.45 arc-78 150.27,90.47 arc-83 103.84,5.31 arc-84 9.42,40.97 arc-114 75.54,152.35 74.55,145.8 arc110 15.49,44.2 arc241 76.73,145.82
N$45
  Top 0.406: R14.2 R19.1 71.5,68.72 +1.P$1
N$46
  Top 0.61: +19+2.P$2 69.34,89.92 +20+2.P$1
N$47
  Top 0.61: +19+2.P$1 76.2,103.12 74.68,105.16 28+2.P$2
N$48
  Top 0.61: 27+2.P$2 59.18,94.74 64.77,94.74 69.09,102.87 71.12,111.25 72.39,115.32 73.15,117.6 77.72,117.6 28+2.P$1
N$49
  Top 0.61: 4+2.P$2 33.02,128.27 arc-34 74.17,146.07 69.85,132.33 72.39,132.33 2+2.P$1
N$50
  Top 0.61: 4+2.P$1 34.54,137.41 arc-20 43.18,143 6+2.P$2
N$51
  Top 0.61: 6+2.P$1 49.28,145.03 arc-23 57.4,148.08 0+2.P$2
N$52
  Top 0.61: 0+2.P$1 64.52,149.35 arc-20 72.9,150.11 5+2.P$2
N$53
  Top 0.61: 5+2.P$1 78.99,149.1 79.5,149.86 arc-21 88.39,149.1 3+2.P$2
N$54
  Top 0.61: 3+2.P$1 94.49,148.34 arc-17 103.38,145.03 1+2.P$2
N$55
  Top 0.61: 1+2.P$1 109.73,142.24 arc-29 116.59,138.18 8+2.P$2
N$56
  Top 0.61: 21+2.P$2 84.69,125.99 81.92,134.17 9+2.P$1
N$57
  Top 0.61: 22+2.P$2 88.39,114.55 86.36,120.65 21+2.P$1
N$58
  Top 0.61: 23+2.P$2 92.65,101.33 89.82,110.06 22+2.P$1
N$59
  Top 0.61: +1+2.P$2 75.69,88.14 81.03,88.14 81.79,86.87 86.87,86.87 +2+2.P$1
N$60
  Top 0.61: +2+2.P$2 86.11,90.68 86.11,92.46 86.61,92.96 90.68,92.96 93.22,90.42 106.68,90.68 24+2.P$1
N$61
  Top 0.61: 23+2.P$1 94.68,99.67 102.75,99.67 24+2.P$2
N$62
  Top 0.61: 2+2.P$2 64.77,117.09 7+2.P$1
N$63
  Top 0.61: 7+2.P$2 63.5,113.03 60.2,101.85 62.23,98.04 27+2.P$1
N$64
  Top 0.61: 9+2.P$2 77.98,137.92 80.37,138.97 78.49,145.29 77.98,145.8 arc-37 117.35,132.08 120.4,133.86 8+2.P$1
N$65
  Top 0.406: +20+2.P$2 64.91,89.18 R15.1 64.49,87.26 R18.2
N$66
  Top 0.406: R8.1 45.21,55.49 +20.P$2 45.83,57.88 R20.2
N$67
  Top 0.406: 43.94,40.64 +20+3.P$1
  Top 0.61: +19+3.P$2 39.88,40.64 43.94,40.64
N$68
  Top 0.61: 28+3.P$2 23.88,22.86 26.92,19.81 30.23,22.86 33.78,21.84 35.56,27.69 39.12,27.69 +19+3.P$1
N$69
  Top 0.61: 27+3.P$2 arc14 18.54,29.72 23.37,29.72 28+3.P$1
N$70
  Top 0.61: 4+3.P$2 arc9 2.03,71.12 4.83,71.12 4.83,69.85 2+3.P$1
N$71
  Top 0.61: 6+3.P$2 arc14 2.79,87.12 5.08,86.61 4+3.P$1
N$72
  Top 0.61: 0+3.P$2 arc10 6.35,101.85 8.64,101.09 6+3.P$1
N$73
  Top 0.61: 0+3.P$1 14.73,115.57 12.95,115.57 arc-12 5+3.P$2
N$74
  Top 0.61: 5+3.P$1 26.16,121.41 arc21 13.46,99.57 17.78,99.57 18.78,98.82 18.54,98.81 18.78,98.03 3+3.P$2
N$75
  Top 0.61: 1+3.P$2 3+3.P$1
N$76
  Top 0.61: 8+3.P$2 33.78,77.47 25.4,84.07 25.4,87.12 1+3.P$1
N$77
  Top 0.61: 21+3.P$2 31.69,96.84 31.75,96.77 34.04,92.71 39.88,91.95 43.18,90.42 9+3.P$1
N$78
  Top 0.61: 21+3.P$1 38.1,99.57 42.93,99.57 22+3.P$2
N$79
  Top 0.61: 23+3.P$2 22+3.P$1
N$80
  Top 0.61: +1+3.P$2 64.77,72.64 +2+3.P$1
N$81
  Top 0.61: +3+3.P$1 +2+3.P$2
N$82
  Top 0.61: +3+3.P$2 49.28,75.18 57.4,78.99 23+3.P$1
N$83
  Top 0.61: 2+3.P$2 arc22 4.83,56.39 7.62,56.39 7.87,55.12 7+3.P$1
N$84
  Top 0.61: 7+3.P$2 arc23 10.41,42.42 13.97,42.42 27+3.P$1
N$85
  Top 0.61: 9+3.P$2 39.62,80.26 8+3.P$1
N$86
  Bottom 0.406: R33.1 98.04,101.85 96.27,103.63 96.27,105.03 R31.1 96.64,109.22 | 96.64,109.22 96.64,109.47 R16.P$2 | D1.A 91.11,115.65 97.54,109.22 96.64,109.22
N$87
  Bottom 0.5: L1.1 61.32,32.77 71.88,32.77 74.21,35.09 Q2.3 90.72,35.09 92.46,36.83 91.84,36.83 D2.A
N$88  (1 unrouted)
  Bottom 0.406: R1.1 107.47,74.17 112.01,73.41 U$1.P$5 104.39,73.41 102.11,71.12 U$2.1
  Bottom 0.5: R36.2 100.88,55.67 PH1.2 95.5,54.61 101.85,51.82 111.76,57.4 112.01,64.01 | 112.01,73.41 112.01,67.06
N$91
  Bottom 0.406: R30.2 104.78,105.16 106.43,105.16 107.32,104.26 R32.2 107.32,99.29 R16.P$1 104.78,92.46 82.8,92.46 D3.C 82.55,95.07 D4.C
  Bottom 0.5: 82.8,92.46 82.8,88.81 R2.2
N$92
  Bottom 0.406: 41.66,100.58 41.85,100.39 R22.P$1 43.43,100.84 | R26.2 46.69,102.21 R27.2 44.8,102.21 43.81,101.22 43.43,100.84 | 43.43,100.84
  Bottom 0.5: Q5.3 47.24,97.79 43.81,101.22
N$93
  Bottom 0.406: 82.8,98.61 D3.A 83.06,98.73 | 83.06,98.73 AC1.P$1 | 83.06,98.73 D6.C
N$94
  Bottom 0.5: Q2.1 74.43,44.63 P4ZD2.C | R13.2 74.02,42.8 Q2.1 | Q3.3 71.88,44.94 Q2.1
N$95
  Bottom 0.406: R4.2 94.49,71.12 U$1.P$3
  Bottom 0.5: U$2.4 99.82,63.75 99.82,62.48 90.68,62.48 R4.2
N$96  (1 unrouted)
  Bottom 0.5: 98.3,88.14 R44.1 | 98.3,88.14 100.03,88.14 P4ZD1.C 103.71,88.57 C5.2 106.91,88.27 R21.2 113.28,87.88 118.11,84.84 118.11,68.33 117.6,66.04 U$1.P$8 | U$2.6 98.3,81.28 98.3,83.06 | 98.3,88.14 98.3,85.85
N$97
  Bottom 0.5: R2.1 90.26,88.39 R44.2
N$98
  Bottom 0.5: Q1.1 78.38,54.17 R6.1
N$99
  Bottom 0.406: R23.2 49.05,108.99 R26.1
N$100
  Bottom 0.406: R25.2 51.41,106.78 R27.1
N$101
  Bottom 0.5: Q1.3 84.56,55.12 R5.2
N$102  (1 unrouted)
  Bottom 0.5: 102.11,61.98 U$2.3 | U$1.P$4 87.38,73.41 86.36,72.39 86.11,61.72 | R6.2 86.11,61.72 | 100.33,59.69 99.06,60.96 86.11,61.72
N$103
  Bottom 0.5: P4ZD3.C 50.4,82.23 Q4.1 45.3,84.09 R24.2
N$104
  Bottom 0.5: R29.1 48.28,94.49 Q5.1 48.19,92.21 P4ZD7.C
N$105
  Bottom 0.5: Q2.2 78.99,45.14 P4ZD2.A | R9.1 78.32,45.81 P4ZD2.A | P4ZD2.A 80.52,47.32 R3.1 81,48.51 84.33,48.51 85.85,50.04 R5.1
N$106
  Bottom 0.5: R7.1 55.27,94.74 R29.2
N$107
  Bottom 0.406: R31.2 R30.1
N$108
  Bottom 0.406: R32.1 102.24,101.6 R33.2
N$109
  Bottom 0.5: Q3.1 70.93,49.34 71.88,50.29 75.35,50.29 R9.2
VDD  (1 unrouted)
  Bottom 0.406: U$1.P$2 97.28,68.33 98.04,68.33
  Bottom 0.5: 97.28,68.33 97.54,68.58 97.54,75.95 90.17,83.31 71.63,83.31 68.5,80.19 C3.+ 56.75,80.33 Q4.2 | C1.2 104.69,59.05 R36.3 103.77,58.19 PH1.1 100.58,61.47 | U$2.5 98.04,68.33 98.55,64.01
VSS  (1 unrouted)
  Bottom 0.406: 104.14,68.33 U$2.2
  Bottom 0.5: R36.1 105.41,56.14 105.66,56.39 107.19,56.39 108.71,57.91 108.71,60.45 107.31,61.85 C1.1 104.14,62.74 104.14,68.33 U$1.P$7 | P4ZD7.A 49.94,86.54 P4ZD3.A 56.55,86.54 C3.- 75.87,86.19 77.72,84.33 99.62,84.33 P4ZD1.A 100.76,85.47 C5.1 104.03,85.45 R21.1 110.24,84.33 R1.2 114.81,75.44 114.81,68.33
(copper drawn outside any net)
  shapes: Bottom circle x3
